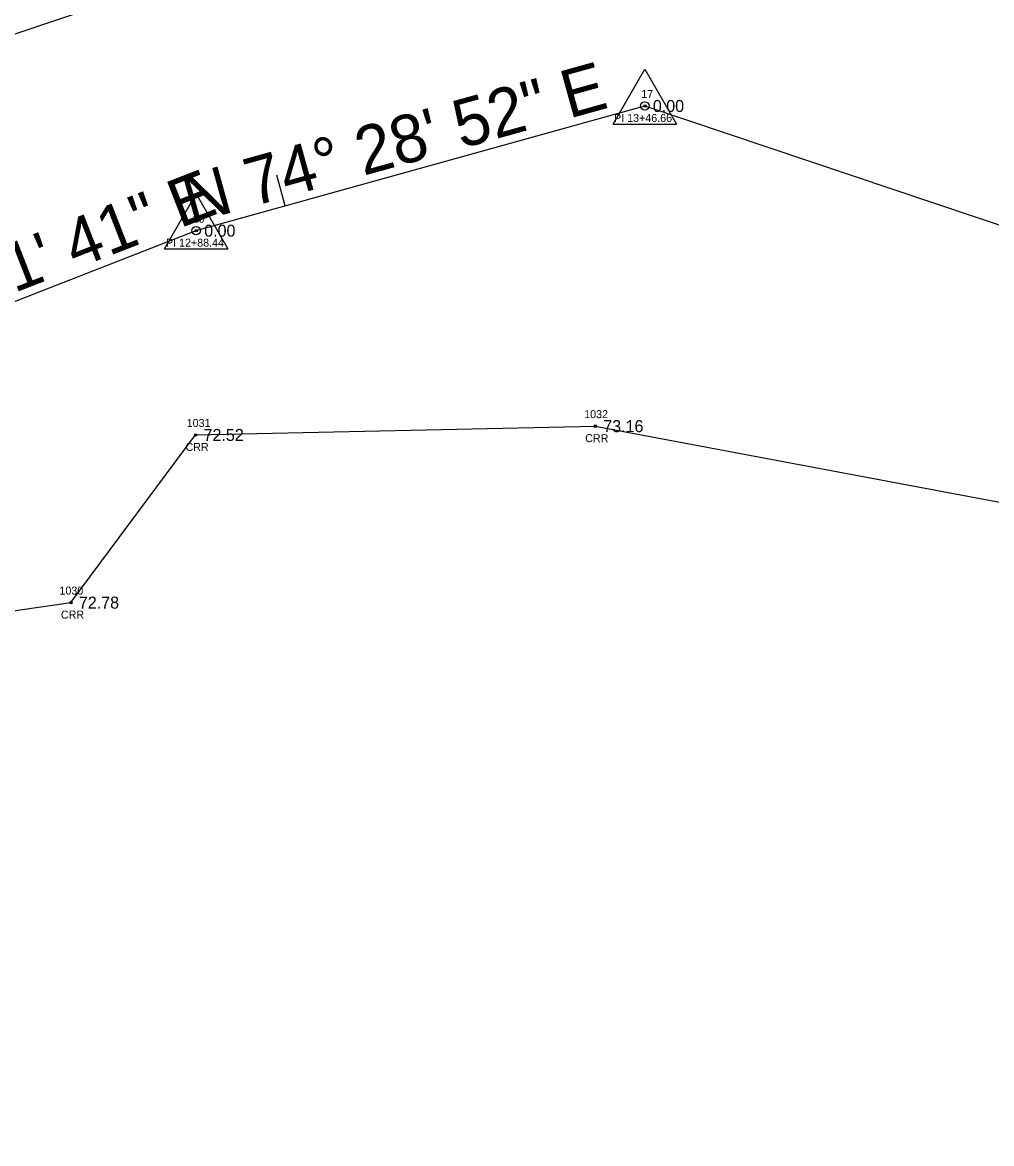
# Model space of a CAD drawing. Extents: x 2505249 to 2506333, y 912937 to 914171.
# Drawn here: x 2505870.1 to 2505991.3, y 913385.5 to 913525.6 of the extents above; entities that cross this region are included whole.
import ezdxf

# ---------------------------------------------------------------- set-up
doc = ezdxf.new("R2010")
doc.units = 0
for name, color, linetype in [('RD_EX_H2O', 7, 'Continuous'), ('RD_EX_H2O_txCode', 7, 'Continuous'), ('RD_EX_TX_H2O_ELEV', 7, 'Continuous'), ('RD_HC_Cl', 7, 'Continuous'), ('RD_HC_Data', 7, 'Continuous'), ('RD_HC_Data_Tic', 7, 'Continuous'), ('RD_HC_Survey_ELEV', 7, 'Continuous'), ('RD_HC_txCode', 7, 'Continuous'), ('RD_SMD_Locator', 7, 'Continuous')]:
    doc.layers.add(name, color=color, linetype=linetype)

msp = doc.modelspace()

# ---------------------------------------------------------------- linework, layer by layer
at = {"layer": 'RD_EX_H2O'}
for points in [[(2505762.26, 913658.11), (2505746.15, 913644.25), (2505726.47, 913615.21), (2505674.21, 913628.01), (2505666.25, 913620.58), (2505714.6, 913592.15), (2505793.9, 913560.45), (2505801.32, 913552.8), (2505803.7, 913539.77), (2505832.63, 913516.96), (2505848.42, 913517.19), (2505881.86, 913528.44), (2505910.2, 913538.78), (2505939.3, 913544.45), (2505946.25, 913542.54), (2505974.65, 913535.18), (2506004.11, 913524.7), (2506052.03, 913515.47), (2506115.49, 913494.68), (2506138.05, 913548.89)], [(2505789.47, 913464.31), (2505795.69, 913463.1), (2505812.13, 913464.37), (2505832.03, 913446.73), (2505876.17, 913453.08), (2505891.76, 913474.03), (2505941.74, 913475.13), (2505995.42, 913465.05), (2506040.13, 913447.4), (2506076.3, 913432.47), (2506096.96, 913385.48)]]:
    msp.add_lwpolyline(points, dxfattribs=at)
at = {"layer": 'RD_HC_Cl'}
for p, q in [((2505891.84, 913499.56), (2505947.94, 913515.14)), ((2505947.94, 913515.14), (2506096.51, 913465.31)), ((2505846.35, 913481.82), (2505891.84, 913499.56))]:
    msp.add_line(p, q, dxfattribs=at)
at = {"layer": 'RD_HC_Data'}
for p, q in [((2505943.97, 913512.85), (2505947.94, 913519.73)), ((2505947.94, 913519.73), (2505951.91, 913512.85)), ((2505943.97, 913512.85), (2505951.91, 913512.85)), ((2505887.87, 913497.27), (2505891.85, 913504.15)), ((2505891.85, 913504.15), (2505895.81, 913497.27)), ((2505887.87, 913497.27), (2505895.81, 913497.27))]:
    msp.add_line(p, q, dxfattribs=at)
for centre in [(2505947.94, 913515.14), (2505891.84, 913499.56)]:
    msp.add_circle(centre, 0.529, dxfattribs=at)
at = {"layer": 'RD_HC_Data_Tic'}
msp.add_line((2505902.98, 913502.66), (2505901.91, 913506.51), dxfattribs=at)
at = {"layer": 'RD_SMD_Locator'}
for centre in [(2505947.94, 913515.14), (2505891.84, 913499.56), (2505941.74, 913475.13), (2505891.76, 913474.03), (2505876.17, 913453.08)]:
    msp.add_circle(centre, 0.15, dxfattribs=at)

# ---------------------------------------------------------------- texts
at = {"layer": 'RD_EX_H2O_txCode'}
for s, p in [('1031', (2505890.65, 913475.03)), ('1032', (2505940.35, 913476.13)), ('CRR', (2505890.5, 913472.03)), ('CRR', (2505940.48, 913473.13)), ('1030', (2505874.74, 913454.08)), ('CRR', (2505874.92, 913451.08))]:
    msp.add_text(s, height=1, dxfattribs=at).set_placement(p)
at = {"layer": 'RD_EX_TX_H2O_ELEV'}
for s, p in [('73.16', (2505942.74, 913474.38)), ('72.52', (2505892.76, 913473.28)), ('72.78', (2505877.17, 913452.33))]:
    msp.add_text(s, height=1.5, dxfattribs=at).set_placement(p)
at = {"layer": 'RD_HC_Data'}
for s, rotation, p in [('N 74%%d 28\' 52" E', 15.519, (2505891.15, 913500.41)), ('N 68%%d 41\' 41" E', 21.3052, (2505844.06, 913482))]:
    msp.add_text(s, height=6, rotation=rotation, dxfattribs=at).set_placement(p)
at = {"layer": 'RD_HC_Survey_ELEV'}
for p in [(2505948.94, 913514.39), (2505892.84, 913498.81)]:
    msp.add_text('0.00', height=1.5, dxfattribs=at).set_placement(p)
at = {"layer": 'RD_HC_txCode'}
for s, p in [('17', (2505947.49, 913516.14)), ('PI 13+46.66', (2505944.09, 913513.14)), ('16', (2505891.37, 913500.56)), ('PI 12+88.44', (2505888.06, 913497.56))]:
    msp.add_text(s, height=1, dxfattribs=at).set_placement(p)

doc.saveas('drawing.dxf')
